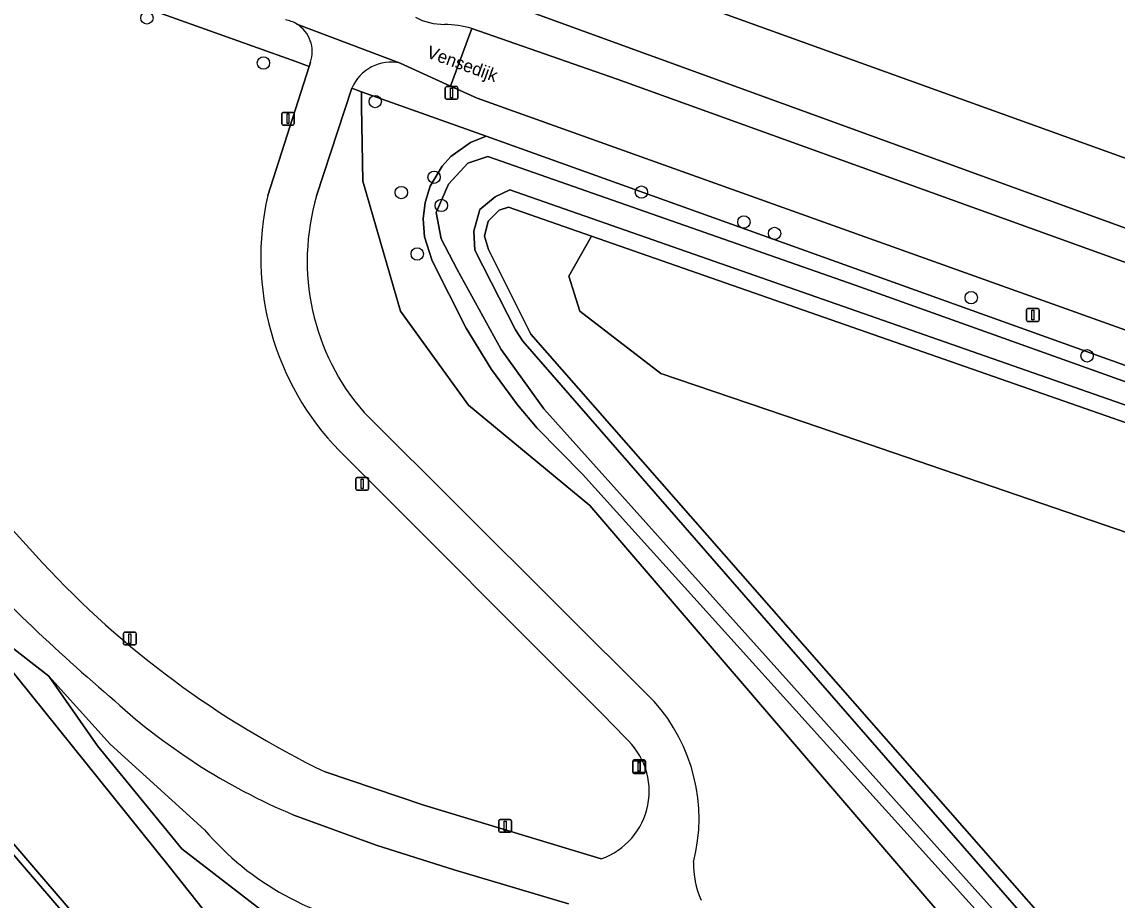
# Model space of a CAD drawing. Extents: x 156061 to 157804, y 383437 to 385640.
# Drawn here: x 156290.3 to 156376.7, y 385104.6 to 385173.9 of the extents above; entities that cross this region are included whole.
import ezdxf

# ---------------------------------------------------------------- set-up
doc = ezdxf.new("R2010")
doc.units = 0
for name, color, linetype in [('IMGEO_Berm_groen', 7, 'Continuous'), ('IMGEO_Boom', 7, 'Continuous'), ('IMGEO_Fietspad_gesloten', 7, 'Continuous'), ('IMGEO_Grasland_overig', 7, 'Continuous'), ('IMGEO_Groenvoorziening', 7, 'Continuous'), ('IMGEO_Kademuur', 7, 'Continuous'), ('IMGEO_Lichtmast', 7, 'Continuous'), ('IMGEO_Loofbos', 7, 'Continuous'), ('IMGEO_Oever', 7, 'Continuous'), ('IMGEO_Openbare_ruimte_label', 7, 'Continuous'), ('IMGEO_Rijbaan_lokaal_gesloten', 7, 'Continuous'), ('IMGEO_Rijbaan_lokaal_open', 7, 'Continuous'), ('IMGEO_Verkeersbordpaal', 7, 'Continuous'), ('IMGEO_Waterloop', 7, 'Continuous')]:
    doc.layers.add(name, color=color, linetype=linetype)

msp = doc.modelspace()

# ---------------------------------------------------------------- linework, layer by layer
at = {"layer": 'IMGEO_Berm_groen'}
for points in [[(156244.391, 385176.164), (156248.071, 385171.713), (156252.284, 385167.631), (156256.605, 385163.179), (156266.968, 385149.544), (156268.887, 385147.313), (156275.588, 385139.525), (156279.935, 385133.606), (156284.827, 385128.152), (156285.498, 385127.632), (156292.415, 385122.267), (156297.254, 385116.885), (156304.708, 385110.143)], [(156333.431, 385104.287), (156324.419, 385106.981), (156318.255, 385108.918), (156311.756, 385111.305)]]:
    msp.add_lwpolyline(points, dxfattribs=at)
for centre, radius, start, end in [((156388.859, 385228.442), 141.469, 222.52663, 225.83773), ((156388.957, 385228.642), 141.681, 225.86584, 229.64779), ((156331.057, 385157.224), 49.81, 227.2108, 247.20128), ((156321.959, 385124.85), 22.669, 220.44954, 262.06664)]:
    msp.add_arc(centre, radius, start, end, dxfattribs=at)
at = {"layer": 'IMGEO_Boom'}
for centre in [(156300.165, 385174.203), (156309.365, 385170.649), (156318.186, 385167.605), (156322.833, 385161.634), (156320.246, 385160.421), (156339.198, 385160.457), (156323.406, 385159.406), (156347.285, 385158.097), (156349.705, 385157.201), (156321.501, 385155.575), (156365.227, 385152.129), (156374.372, 385147.541)]:
    msp.add_circle(centre, 0.489, dxfattribs=at)
at = {"layer": 'IMGEO_Fietspad_gesloten'}
for points in [[(156291.925, 385131.208), (156286.722, 385136.92), (156262.712, 385164.588), (156232.407, 385199.152)], [(156320.162, 385170.636), (156311.996, 385173.718)], [(156313.068, 385170.708), (156312.964, 385170.382), (156309.704, 385160.199)], [(156313.558, 385160.157), (156316.341, 385168.651)], [(156340.205, 385120.26), (156317.31, 385143.059)], [(156315.361, 385140.046), (156336.134, 385119.263), (156337.904, 385117.409)], [(156336.032, 385107.853), (156322.012, 385112.071), (156314.224, 385114.708)], [(156311.756, 385111.305), (156318.255, 385108.918), (156324.419, 385106.981), (156333.431, 385104.287)]]:
    msp.add_lwpolyline(points, dxfattribs=at)
for centre, radius, start, end in [((156310.66, 385171.546), 2.55, 340.80347, 58.40285), ((156319.453, 385167.332), 3.38, 77.88208, 157.02145), ((156331.047, 385155.32), 21.894, 167.12275, 224.23639), ((156330.983, 385155.02), 18.166, 163.57374, 221.17998), ((156388.859, 385228.442), 141.469, 222.52663, 225.83773), ((156346.962, 385182.269), 75.075, 222.85431, 244.14699), ((156388.957, 385228.642), 141.681, 225.86584, 229.64779), ((156331.057, 385157.224), 49.81, 227.2108, 247.20128), ((156329.916, 385111.018), 13.83, 345.65024, 41.93227), ((156334.172, 385113.179), 5.641, 289.25253, 48.57995), ((156350.43, 385107.435), 7.117, 178.7545, 203.54912)]:
    msp.add_arc(centre, radius, start, end, dxfattribs=at)
at = {"layer": 'IMGEO_Grasland_overig'}
for points in [[(156312.964, 385170.382), (156311.916, 385170.758), (156294.952, 385176.85), (156286.728, 385180.209), (156281.342, 385182.658), (156280.613, 385181.597), (156272.418, 385169.582), (156264.333, 385165.422), (156262.712, 385164.588), (156286.722, 385136.92), (156291.925, 385131.208)], [(156559.946, 385091.941), (156513.087, 385108.31), (156319.707, 385178.59)], [(156325.805, 385173.38), (156337.293, 385169.362), (156500, 385110.725), (156556.615, 385090.377)], [(156309.704, 385160.199), (156312.964, 385170.382)], [(156392.382, 385074.146), (156334.554, 385138.206), (156330.958, 385141.834), (156329.423, 385143.664), (156327.375, 385146.454), (156325.358, 385149.726), (156322.682, 385155.044), (156322.069, 385156.916), (156321.963, 385158.352), (156322.118, 385159.638), (156322.526, 385160.917), (156323.465, 385162.502), (156324.159, 385163.263), (156325.695, 385164.367), (156326.933, 385164.881), (156317.115, 385168.375), (156317.115, 385167.253), (156317.21, 385161.313), (156320.169, 385151.071), (156325.559, 385143.656), (156335.129, 385135.722), (156365.849, 385099.914), (156390.104, 385073.29)], [(156337.904, 385117.409), (156336.134, 385119.263), (156315.361, 385140.046)], [(156314.224, 385114.708), (156322.012, 385112.071), (156336.032, 385107.853)]]:
    msp.add_lwpolyline(points, dxfattribs=at)
for centre, radius, start, end in [((156323.649, 385178.623), 4.93, 242.32472, 270.10765), ((156323.573, 385165.591), 8.103, 74.01153, 89.39963), ((156331.047, 385155.32), 21.894, 167.12275, 224.23639), ((156346.962, 385182.269), 75.075, 222.85431, 244.14699), ((156334.172, 385113.179), 5.641, 289.25253, 48.57995)]:
    msp.add_arc(centre, radius, start, end, dxfattribs=at)
at = {"layer": 'IMGEO_Groenvoorziening'}
for points in [[(156327.268, 385181.212), (156500, 385119.001), (156514.993, 385113.601), (156543.545, 385103.317), (156544.01, 385104.644), (156544.923, 385107.249), (156549.717, 385105.569), (156550.566, 385105.271), (156549.653, 385102.666), (156553.4, 385101.352), (156563.924, 385130.884), (156576.52, 385168.23), (156585.869, 385195.589)], [(156294.952, 385176.85), (156311.916, 385170.758), (156312.964, 385170.382), (156313.068, 385170.708)], [(156590.926, 385073.627), (156578.058, 385077.449), (156567.974, 385081.116), (156557.53, 385085.067), (156500, 385105.742), (156431.778, 385130.12), (156326.224, 385167.859), (156324.12, 385168.823), (156320.162, 385170.636)], [(156317.21, 385161.313), (156317.115, 385167.253), (156317.115, 385168.375), (156316.467, 385168.606), (156316.341, 385168.651), (156313.558, 385160.157)], [(156316.341, 385168.651), (156316.467, 385168.606), (156317.115, 385168.375), (156326.933, 385164.881), (156430.956, 385127.576), (156429.845, 385123.974), (156435.058, 385119.831), (156500, 385096.915), (156553.673, 385077.975), (156566.959, 385073.059), (156570.736, 385071.384)], [(156376.743, 385057.501), (156377.282, 385052.547), (156377.415, 385051.322), (156379.934, 385052.112), (156379.507, 385054.215), (156379.044, 385056.491), (156379.879, 385057.811), (156382.111, 385059.201), (156391.94, 385067.342), (156390.104, 385073.29), (156365.849, 385099.914), (156335.129, 385135.722), (156325.559, 385143.656), (156320.169, 385151.071), (156317.21, 385161.313)], [(156317.31, 385143.059), (156340.205, 385120.26)], [(156273.739, 385127.523), (156294.581, 385103.266), (156312.704, 385082.367), (156314.584, 385080.217), (156322.049, 385086.448), (156318.939, 385091.466), (156309.939, 385097.114), (156301.92, 385107.255), (156285.498, 385127.632)], [(156292.415, 385122.267), (156285.498, 385127.632), (156301.92, 385107.255), (156309.939, 385097.114), (156318.939, 385091.466), (156322.049, 385086.448), (156314.584, 385080.217), (156321.835, 385071.923)], [(156337.976, 385053.295), (156339.697, 385051.3), (156357.105, 385066.151), (156338.147, 385086.267), (156326.598, 385093.433), (156321.199, 385099.683), (156317, 385100.045), (156310.159, 385103.07), (156302.922, 385108.634), (156296.262, 385116.752), (156292.415, 385122.267)]]:
    msp.add_lwpolyline(points, dxfattribs=at)
for points in [[(156327.268, 385181.212), (156321.373, 385183.335), (156321.21, 385182.863), (156319.707, 385178.59), (156513.087, 385108.31), (156514.993, 385113.601), (156500, 385119.001)], [(156335.247, 385156.992), (156328.695, 385159.279), (156327.974, 385159.033), (156327.092, 385158.162), (156326.808, 385156.991), (156327.119, 385155.925), (156330.459, 385149.238), (156374.842, 385098.661), (156408.667, 385114.629), (156421.153, 385114.774), (156391.849, 385078.327), (156393.968, 385075.527), (156435.058, 385119.831), (156429.845, 385123.974), (156428.992, 385122.179), (156415.926, 385125.082), (156410.845, 385122.179), (156353.209, 385141.923), (156340.723, 385146.133), (156334.335, 385151.069), (156333.464, 385153.828)], [(156335.247, 385156.992), (156333.464, 385153.828), (156334.335, 385151.069), (156340.723, 385146.133), (156353.209, 385141.923), (156410.845, 385122.179), (156415.926, 385125.082), (156428.992, 385122.179), (156429.845, 385123.974)]]:
    msp.add_lwpolyline(points, close=True, dxfattribs=at)
for centre, radius, start, end in [((156310.67, 385171.573), 2.522, 58.28953, 80.37627), ((156310.66, 385171.546), 2.55, 340.80347, 58.40285), ((156319.453, 385167.332), 3.38, 77.88208, 157.02145), ((156330.983, 385155.02), 18.166, 163.57374, 221.17998), ((156329.916, 385111.018), 13.83, 345.65024, 41.93227), ((156350.43, 385107.435), 7.117, 178.7545, 203.54912)]:
    msp.add_arc(centre, radius, start, end, dxfattribs=at)
at = {"layer": 'IMGEO_Kademuur'}
msp.add_lwpolyline([(156324.937, 385068.374), (156324.909, 385068.406), (156321.835, 385071.923), (156314.584, 385080.217), (156312.704, 385082.367), (156294.581, 385103.266), (156273.739, 385127.523), (156258.702, 385145.004), (156258.194, 385145.595), (156256.777, 385147.242), (156256.36, 385146.883), (156273.322, 385127.165), (156294.164, 385102.907), (156312.29, 385082.006), (156324.538, 385067.995)], close=True, dxfattribs=at)
at = {"layer": 'IMGEO_Lichtmast'}
for p, q in [((156323.72, 385167.88), (156323.72, 385168.68)), ((156323.72, 385168.68), (156323.72, 385167.88)), ((156323.82, 385168.78), (156324.61, 385168.78)), ((156324.61, 385168.78), (156323.82, 385168.78)), ((156324.71, 385168.68), (156324.71, 385167.88)), ((156324.71, 385167.88), (156324.71, 385168.68)), ((156324.61, 385167.78), (156323.82, 385167.78)), ((156323.82, 385167.78), (156324.61, 385167.78)), ((156310.807, 385165.851), (156310.807, 385166.651)), ((156310.807, 385166.651), (156310.807, 385165.851)), ((156310.907, 385166.751), (156311.697, 385166.751)), ((156311.697, 385166.751), (156310.907, 385166.751)), ((156311.797, 385166.651), (156311.797, 385165.851)), ((156311.797, 385165.851), (156311.797, 385166.651)), ((156311.697, 385165.751), (156310.907, 385165.751)), ((156310.907, 385165.751), (156311.697, 385165.751)), ((156316.666, 385137.039), (156316.666, 385137.839)), ((156316.666, 385137.839), (156316.666, 385137.039)), ((156316.766, 385137.939), (156317.556, 385137.939)), ((156317.556, 385137.939), (156316.766, 385137.939)), ((156317.656, 385137.839), (156317.656, 385137.039)), ((156317.656, 385137.039), (156317.656, 385137.839)), ((156317.556, 385136.939), (156316.766, 385136.939)), ((156316.766, 385136.939), (156317.556, 385136.939)), ((156298.325, 385124.821), (156298.325, 385125.621)), ((156298.325, 385125.621), (156298.325, 385124.821)), ((156298.425, 385125.721), (156299.215, 385125.721)), ((156299.215, 385125.721), (156298.425, 385125.721)), ((156299.315, 385125.621), (156299.315, 385124.821)), ((156299.315, 385124.821), (156299.315, 385125.621)), ((156299.215, 385124.721), (156298.425, 385124.721)), ((156298.425, 385124.721), (156299.215, 385124.721)), ((156338.512, 385114.683), (156338.512, 385115.483)), ((156338.512, 385115.483), (156338.512, 385114.683)), ((156338.519, 385114.75), (156338.519, 385115.55)), ((156338.519, 385115.55), (156338.519, 385114.75)), ((156338.612, 385115.583), (156339.402, 385115.583)), ((156339.402, 385115.583), (156338.612, 385115.583)), ((156338.619, 385115.65), (156339.409, 385115.65)), ((156339.409, 385115.65), (156338.619, 385115.65)), ((156339.502, 385115.483), (156339.502, 385114.683)), ((156339.502, 385114.683), (156339.502, 385115.483)), ((156339.509, 385115.55), (156339.509, 385114.75)), ((156339.509, 385114.75), (156339.509, 385115.55)), ((156339.402, 385114.583), (156338.612, 385114.583)), ((156338.612, 385114.583), (156339.402, 385114.583)), ((156339.409, 385114.65), (156338.619, 385114.65)), ((156338.619, 385114.65), (156339.409, 385114.65)), ((156327.941, 385110.043), (156327.941, 385110.843)), ((156327.941, 385110.843), (156327.941, 385110.043)), ((156328.041, 385110.943), (156328.831, 385110.943)), ((156328.831, 385110.943), (156328.041, 385110.943)), ((156328.931, 385110.843), (156328.931, 385110.043)), ((156328.931, 385110.043), (156328.931, 385110.843)), ((156328.831, 385109.943), (156328.041, 385109.943)), ((156328.041, 385109.943), (156328.831, 385109.943))]:
    msp.add_line(p, q, dxfattribs=at)
for points in [[(156324.14, 385168.655), (156324.29, 385168.655), (156324.29, 385167.905), (156324.14, 385167.905), (156324.14, 385168.655)], [(156311.227, 385166.626), (156311.377, 385166.626), (156311.377, 385165.876), (156311.227, 385165.876), (156311.227, 385166.626)], [(156317.086, 385137.814), (156317.236, 385137.814), (156317.236, 385137.064), (156317.086, 385137.064), (156317.086, 385137.814)], [(156298.745, 385125.596), (156298.895, 385125.596), (156298.895, 385124.846), (156298.745, 385124.846), (156298.745, 385125.596)], [(156338.932, 385115.458), (156339.082, 385115.458), (156339.082, 385114.708), (156338.932, 385114.708), (156338.932, 385115.458)], [(156338.939, 385115.525), (156339.089, 385115.525), (156339.089, 385114.775), (156338.939, 385114.775), (156338.939, 385115.525)], [(156328.361, 385110.818), (156328.511, 385110.818), (156328.511, 385110.068), (156328.361, 385110.068), (156328.361, 385110.818)]]:
    msp.add_lwpolyline(points, dxfattribs=at)
for centre, start, end in [((156323.82, 385168.68), 90, 180), ((156323.82, 385168.68), 90, 180), ((156324.61, 385168.68), 0, 90), ((156324.61, 385168.68), 360, 90), ((156323.82, 385167.88), 180, 270), ((156323.82, 385167.88), 180, 270), ((156324.61, 385167.88), 270, 0), ((156324.61, 385167.88), 270, 0), ((156310.907, 385166.651), 90, 180), ((156310.907, 385166.651), 90, 180), ((156311.697, 385166.651), 0, 90), ((156311.697, 385166.651), 360, 90), ((156310.907, 385165.851), 180, 270), ((156310.907, 385165.851), 180, 270), ((156311.697, 385165.851), 270, 0), ((156311.697, 385165.851), 270, 0), ((156316.766, 385137.839), 90, 180), ((156316.766, 385137.839), 90, 180), ((156317.556, 385137.839), 0, 90), ((156317.556, 385137.839), 360, 90), ((156316.766, 385137.039), 180, 270), ((156316.766, 385137.039), 180, 270), ((156317.556, 385137.039), 270, 0), ((156317.556, 385137.039), 270, 0), ((156298.425, 385125.621), 90, 180), ((156298.425, 385125.621), 90, 180), ((156299.215, 385125.621), 0, 90), ((156299.215, 385125.621), 360, 90), ((156298.425, 385124.821), 180, 270), ((156298.425, 385124.821), 180, 270), ((156299.215, 385124.821), 270, 0), ((156299.215, 385124.821), 270, 0), ((156338.612, 385115.483), 90, 180), ((156338.612, 385115.483), 90, 180), ((156338.619, 385115.55), 90, 180), ((156338.619, 385115.55), 90, 180), ((156339.402, 385115.483), 0, 90), ((156339.402, 385115.483), 360, 90), ((156339.409, 385115.55), 0, 90), ((156339.409, 385115.55), 360, 90), ((156338.612, 385114.683), 180, 270), ((156338.612, 385114.683), 180, 270), ((156338.619, 385114.75), 180, 270), ((156338.619, 385114.75), 180, 270), ((156339.402, 385114.683), 270, 0), ((156339.402, 385114.683), 270, 0), ((156339.409, 385114.75), 270, 0), ((156339.409, 385114.75), 270, 0), ((156328.041, 385110.843), 90, 180), ((156328.041, 385110.843), 90, 180), ((156328.831, 385110.843), 0, 90), ((156328.831, 385110.843), 360, 90), ((156328.041, 385110.043), 180, 270), ((156328.041, 385110.043), 180, 270), ((156328.831, 385110.043), 270, 0), ((156328.831, 385110.043), 270, 0)]:
    msp.add_arc(centre, 0.1, start, end, dxfattribs=at)
at = {"layer": 'IMGEO_Loofbos'}
msp.add_lwpolyline([(156304.708, 385110.143), (156297.254, 385116.885), (156292.415, 385122.267), (156296.262, 385116.752), (156302.922, 385108.634), (156310.159, 385103.07), (156317, 385100.045), (156321.199, 385099.683), (156326.598, 385093.433), (156338.147, 385086.267), (156357.105, 385066.151), (156339.697, 385051.3), (156349.929, 385039.44), (156369.878, 385016.482), (156395.918, 384986.359), (156412.705, 384966.973)], dxfattribs=at)
msp.add_arc((156321.959, 385124.85), 22.669, 220.44954, 262.06664, dxfattribs=at)
at = {"layer": 'IMGEO_Oever'}
for points in [[(156430.956, 385127.576), (156326.933, 385164.881), (156325.695, 385164.367), (156324.159, 385163.263), (156323.465, 385162.502), (156322.526, 385160.917), (156322.118, 385159.638), (156321.963, 385158.352), (156322.069, 385156.916), (156322.682, 385155.044), (156325.358, 385149.726), (156327.375, 385146.454), (156329.423, 385143.664), (156330.958, 385141.834), (156334.554, 385138.206), (156392.382, 385074.146)], [(156384.995, 385083.44), (156372.426, 385097.76), (156331.492, 385143.365), (156328.137, 385148.036), (156324.655, 385154.363), (156323.382, 385156.762), (156322.999, 385158.843), (156323.976, 385161.094), (156325.505, 385162.75), (156327.076, 385163.259), (156356.078, 385153.111), (156429.029, 385127.038)], [(156428.647, 385125.722), (156328.817, 385160.648), (156327.649, 385160.096), (156326.439, 385159.098), (156325.972, 385157.378), (156326.036, 385155.871), (156329.263, 385149.586), (156329.836, 385148.695), (156386.439, 385083.748)], [(156386.617, 385085.242), (156374.842, 385098.661), (156330.459, 385149.238), (156327.119, 385155.925), (156326.808, 385156.991), (156327.092, 385158.162), (156327.974, 385159.033), (156328.695, 385159.279), (156335.247, 385156.992), (156429.845, 385123.974)]]:
    msp.add_lwpolyline(points, dxfattribs=at)
at = {"layer": 'IMGEO_Rijbaan_lokaal_gesloten'}
for points in [[(156337.293, 385169.362), (156325.805, 385173.38), (156324.12, 385168.823), (156326.224, 385167.859), (156431.778, 385130.12), (156500, 385105.742), (156557.53, 385085.067), (156567.974, 385081.116), (156578.058, 385077.449), (156590.926, 385073.627), (156601.317, 385070.529), (156604.139, 385073.809), (156569.753, 385086.114)], [(156556.615, 385090.377), (156500, 385110.725), (156337.293, 385169.362)]]:
    msp.add_lwpolyline(points, dxfattribs=at)
at = {"layer": 'IMGEO_Rijbaan_lokaal_open'}
msp.add_lwpolyline([(156311.996, 385173.718), (156320.162, 385170.636), (156324.12, 385168.823), (156325.805, 385173.38)], dxfattribs=at)
for centre, radius, start, end in [((156310.67, 385171.573), 2.522, 58.28953, 80.37627), ((156323.649, 385178.623), 4.93, 242.32472, 270.10765), ((156323.573, 385165.591), 8.103, 74.01153, 89.39963)]:
    msp.add_arc(centre, radius, start, end, dxfattribs=at)
at = {"layer": 'IMGEO_Verkeersbordpaal'}
for p, q in [((156369.699, 385151.261), (156370.489, 385151.261)), ((156370.489, 385151.261), (156369.699, 385151.261)), ((156369.599, 385150.361), (156369.599, 385151.161)), ((156369.599, 385151.161), (156369.599, 385150.361)), ((156370.589, 385151.161), (156370.589, 385150.361)), ((156370.589, 385150.361), (156370.589, 385151.161)), ((156370.489, 385150.261), (156369.699, 385150.261)), ((156369.699, 385150.261), (156370.489, 385150.261))]:
    msp.add_line(p, q, dxfattribs=at)
msp.add_lwpolyline([(156370.019, 385151.136), (156370.169, 385151.136), (156370.169, 385150.386), (156370.019, 385150.386), (156370.019, 385151.136)], dxfattribs=at)
for centre, start, end in [((156369.699, 385151.161), 90, 180), ((156369.699, 385151.161), 90, 180), ((156370.489, 385151.161), 0, 90), ((156370.489, 385151.161), 360, 90), ((156369.699, 385150.361), 180, 270), ((156369.699, 385150.361), 180, 270), ((156370.489, 385150.361), 270, 0), ((156370.489, 385150.361), 270, 0)]:
    msp.add_arc(centre, 0.1, start, end, dxfattribs=at)
at = {"layer": 'IMGEO_Waterloop'}
for points in [[(156324.073, 385070.602), (156325.517, 385068.933), (156324.909, 385068.406), (156324.937, 385068.374), (156324.538, 385067.995), (156312.29, 385082.006), (156294.164, 385102.907), (156273.322, 385127.165), (156256.36, 385146.883), (156256.777, 385147.242), (156258.194, 385145.595), (156258.746, 385146.253), (156255.063, 385150.406), (156254.53, 385149.743), (156255.773, 385148.315), (156255.358, 385147.954), (156244.779, 385160.106), (156234.347, 385171.939), (156219.209, 385189.383)], [(156429.029, 385127.038), (156356.078, 385153.111), (156327.076, 385163.259), (156325.505, 385162.75), (156323.976, 385161.094), (156322.999, 385158.843), (156323.382, 385156.762), (156324.655, 385154.363), (156328.137, 385148.036), (156331.492, 385143.365), (156372.426, 385097.76), (156384.995, 385083.44)], [(156386.439, 385083.748), (156329.836, 385148.695), (156329.263, 385149.586), (156326.036, 385155.871), (156325.972, 385157.378), (156326.439, 385159.098), (156327.649, 385160.096), (156328.817, 385160.648), (156428.647, 385125.722)]]:
    msp.add_lwpolyline(points, dxfattribs=at)

# ---------------------------------------------------------------- texts
at = {"layer": 'IMGEO_Openbare_ruimte_label'}
msp.add_text('Vensedijk', height=1, rotation=340.18819, dxfattribs=at).set_placement((156322.166, 385171.099))

doc.saveas('drawing.dxf')
